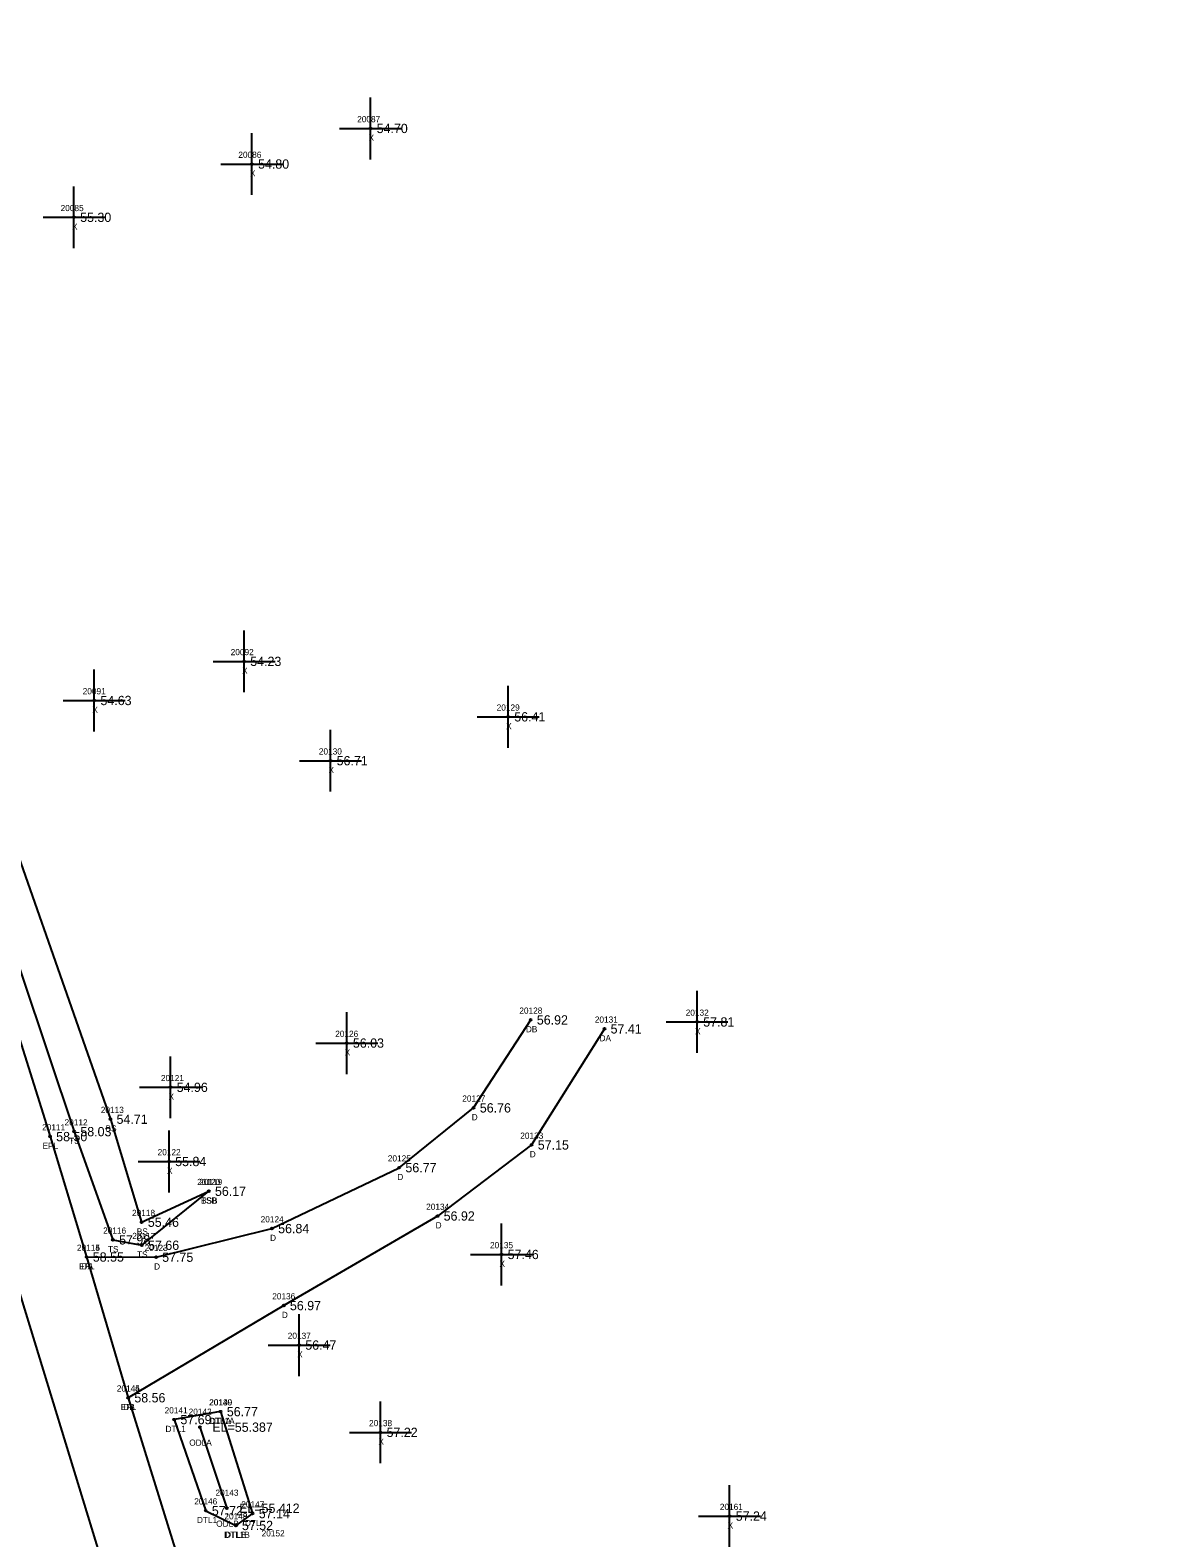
# Model space of a CAD drawing. Extents: x 2396547 to 2397655, y 770185 to 772649.
# Drawn here: x 2396880.4 to 2397062.1, y 771981.7 to 772225.3 of the extents above; entities that cross this region are included whole.
import ezdxf

# ---------------------------------------------------------------- set-up
doc = ezdxf.new("R2010")
doc.units = 0
for name, color, linetype in [('RD_DTM_BkLn1', 7, 'Continuous'), ('RD_DTM_BkLn2', 7, 'Continuous'), ('RD_DTM_BkLn_txCode', 7, 'Continuous'), ('RD_EX_Driveway', 7, 'Continuous'), ('RD_EX_Driveway_txCode', 7, 'Continuous'), ('RD_EX_H2O', 7, 'Continuous'), ('RD_EX_H2O_txCode', 7, 'Continuous'), ('RD_EX_Misc', 7, 'Continuous'), ('RD_EX_Misc_txCode', 7, 'Continuous'), ('RD_EX_Road', 7, 'Continuous'), ('RD_EX_Road_txCode', 7, 'Continuous'), ('RD_EX_TX_Driveway_ELEV', 7, 'Continuous'), ('RD_EX_TX_H2O_ELEV', 7, 'Continuous'), ('RD_EX_TX_Misc_ELEV', 7, 'Continuous'), ('RD_EX_TX_Road_ELEV', 7, 'Continuous'), ('RD_SMD_Locator', 7, 'Continuous')]:
    doc.layers.add(name, color=color, linetype=linetype)

msp = doc.modelspace()

# ---------------------------------------------------------------- linework, layer by layer
at = {"layer": 'RD_DTM_BkLn1'}
msp.add_lwpolyline([(2396669.86, 772614.94), (2396704.28, 772521.49), (2396739.29, 772426.89), (2396775.36, 772328.69), (2396800.21, 772259.35), (2396825.58, 772185.8), (2396852.46, 772104.52), (2396872.48, 772041.55), (2396897.57, 771959.72), (2396918.76, 771888.68), (2396939.09, 771818.34), (2396959.29, 771747.62), (2396993.72, 771617.68), (2397022.56, 771506.67), (2397049.1, 771404.69)], dxfattribs=at)
at = {"layer": 'RD_DTM_BkLn2'}
for points in [[(2396760.04, 772432.43), (2396789.87, 772348.56), (2396819.19, 772264.69), (2396848.46, 772183.36), (2396871.43, 772111.95), (2396893.38, 772049.37), (2396898.43, 772032.73), (2396909.27, 772037.73)], [(2396760.04, 772432.43), (2396760.2, 772413.09), (2396784.34, 772347.64), (2396814.22, 772264.11), (2396842.68, 772182.48), (2396866.31, 772110.61), (2396887.53, 772047.36), (2396893.79, 772029.88), (2396898.47, 772029.01), (2396909.27, 772037.73)]]:
    msp.add_lwpolyline(points, dxfattribs=at)
at = {"layer": 'RD_EX_Driveway'}
for points in [[(2396889.54, 772027.11), (2396900.75, 772027.08), (2396919.48, 772031.7), (2396940.03, 772041.54), (2396952.05, 772051.2), (2396961.26, 772065.41)], [(2396973.17, 772063.96), (2396961.41, 772045.21), (2396946.21, 772033.73), (2396921.38, 772019.26), (2396896.25, 772004.37)]]:
    msp.add_lwpolyline(points, dxfattribs=at)
at = {"layer": 'RD_EX_H2O'}
msp.add_line((2396907.85, 771999.62), (2396912.18, 771986.53), dxfattribs=at)
for points in [[(2396911.19, 772002.13), (2396903.69, 772000.84), (2396908.77, 771986.13), (2396913.63, 771983.74)], [(2396911.19, 772002.13), (2396916.35, 771985.65), (2396913.63, 771983.74)]]:
    msp.add_lwpolyline(points, dxfattribs=at)
at = {"layer": 'RD_EX_Misc'}
for p, q in [((2396935.39, 772204.42), (2396935.39, 772214.42)), ((2396916.23, 772198.67), (2396916.23, 772208.67)), ((2396930.39, 772209.42), (2396940.39, 772209.42)), ((2396911.23, 772203.67), (2396921.23, 772203.67)), ((2396887.5, 772190.06), (2396887.5, 772200.06)), ((2396882.5, 772195.06), (2396892.5, 772195.06)), ((2396914.97, 772118.33), (2396914.97, 772128.33)), ((2396909.97, 772123.33), (2396919.97, 772123.33)), ((2396890.78, 772112.01), (2396890.78, 772122.01)), ((2396957.61, 772109.37), (2396957.61, 772119.37)), ((2396885.78, 772117.01), (2396895.78, 772117.01)), ((2396952.61, 772114.37), (2396962.61, 772114.37)), ((2396928.92, 772102.28), (2396928.92, 772112.28)), ((2396923.92, 772107.28), (2396933.92, 772107.28)), ((2396988.13, 772060.08), (2396988.13, 772070.08)), ((2396931.55, 772056.67), (2396931.55, 772066.67)), ((2396983.13, 772065.08), (2396993.13, 772065.08)), ((2396926.55, 772061.67), (2396936.55, 772061.67)), ((2396903.09, 772049.52), (2396903.09, 772059.52)), ((2396898.09, 772054.52), (2396908.09, 772054.52)), ((2396902.85, 772037.54), (2396902.85, 772047.54)), ((2396897.85, 772042.54), (2396907.85, 772042.54)), ((2396956.54, 772022.52), (2396956.54, 772032.52)), ((2396951.54, 772027.52), (2396961.54, 772027.52)), ((2396923.86, 772007.88), (2396923.86, 772017.88)), ((2396918.86, 772012.88), (2396928.86, 772012.88)), ((2396936.99, 771993.78), (2396936.99, 772003.78)), ((2396931.99, 771998.78), (2396941.99, 771998.78)), ((2396993.38, 771980.25), (2396993.38, 771990.25)), ((2396988.38, 771985.25), (2396998.38, 771985.25))]:
    msp.add_line(p, q, dxfattribs=at)
at = {"layer": 'RD_EX_Road'}
msp.add_lwpolyline([(2396680.92, 772617.84), (2396715.6, 772525.73), (2396750.68, 772430.62), (2396786.3, 772332.21), (2396811.38, 772263.31), (2396839.69, 772181.74), (2396863.75, 772109.83), (2396883.63, 772046.56), (2396889.54, 772027.11), (2396896.25, 772004.37), (2396904.34, 771978.33), (2396908.24, 771964.89), (2396921.74, 771919.68), (2396927.03, 771902.11), (2396950.2, 771821.74), (2396970.47, 771750.68), (2396978.33, 771721.29), (2396990.58, 771675.04), (2397004.94, 771620.49), (2397034.26, 771508.8), (2397061.11, 771410.49), (2397060.64, 771407.04), (2397062.07, 771407.67)], dxfattribs=at)
at = {"layer": 'RD_SMD_Locator'}
for centre in [(2396935.39, 772209.42), (2396916.23, 772203.67), (2396887.5, 772195.06), (2396914.97, 772123.33), (2396890.78, 772117.01), (2396957.61, 772114.37), (2396928.92, 772107.28), (2396961.26, 772065.41), (2396973.17, 772063.96), (2396988.13, 772065.08), (2396931.55, 772061.67), (2396903.09, 772054.52), (2396893.38, 772049.37), (2396952.05, 772051.2), (2396887.53, 772047.36), (2396883.63, 772046.56), (2396961.41, 772045.21), (2396902.85, 772042.54), (2396940.03, 772041.54), (2396909.27, 772037.73), (2396909.27, 772037.73), (2396898.43, 772032.73), (2396946.21, 772033.73), (2396893.79, 772029.88), (2396919.48, 772031.7), (2396898.47, 772029.01), (2396956.54, 772027.52), (2396889.54, 772027.11), (2396889.54, 772027.11), (2396900.75, 772027.08), (2396921.38, 772019.26), (2396923.86, 772012.88), (2396896.25, 772004.37), (2396896.25, 772004.37), (2396903.69, 772000.84), (2396911.19, 772002.13), (2396911.19, 772002.13), (2396907.85, 771999.62), (2396936.99, 771998.78), (2396908.77, 771986.13), (2396912.18, 771986.53), (2396913.63, 771983.74), (2396913.63, 771983.74), (2396916.35, 771985.65), (2396993.38, 771985.25)]:
    msp.add_circle(centre, 0.15, dxfattribs=at)

# ---------------------------------------------------------------- texts
at = {"layer": 'RD_DTM_BkLn_txCode'}
for s, p in [('20112', (2396885.98, 772048.36)), ('20113', (2396891.83, 772050.37)), ('BS', (2396892.6, 772047.37)), ('TS', (2396886.73, 772045.36)), ('20120', (2396907.4, 772038.73)), ('20119', (2396907.72, 772038.73)), ('20118', (2396896.88, 772033.73)), ('TSB', (2396908, 772035.73)), ('BSB', (2396908.02, 772035.73)), ('20116', (2396892.21, 772030.88)), ('20117', (2396896.92, 772030.01)), ('BS', (2396897.65, 772030.73)), ('TS', (2396892.99, 772027.88)), ('TS', (2396897.68, 772027.01))]:
    msp.add_text(s, height=1, dxfattribs=at).set_placement(p)
at = {"layer": 'RD_EX_Driveway_txCode'}
for s, p in [('20128', (2396959.43, 772066.41)), ('DB', (2396960.48, 772063.41)), ('20131', (2396971.62, 772064.96)), ('DA', (2396972.38, 772061.96)), ('20127', (2396950.21, 772052.2)), ('D', (2396951.74, 772049.2)), ('20133', (2396959.58, 772046.21)), ('20125', (2396938.19, 772042.54)), ('D', (2396961.11, 772043.21)), ('D', (2396939.72, 772039.54)), ('20134', (2396944.38, 772034.73)), ('20124', (2396917.65, 772032.7)), ('D', (2396945.91, 772031.73)), ('D', (2396919.17, 772029.7)), ('20115', (2396887.98, 772028.11)), ('20123', (2396898.92, 772028.08)), ('DA', (2396888.74, 772025.11)), ('D', (2396900.44, 772025.08)), ('20136', (2396919.52, 772020.26)), ('D', (2396921.07, 772017.26)), ('20144', (2396894.42, 772005.37)), ('DB', (2396895.47, 772002.37)), ('20152', (2396917.81, 771981.97))]:
    msp.add_text(s, height=1, dxfattribs=at).set_placement(p)
at = {"layer": 'RD_EX_H2O_txCode'}
for s, p in [('20140', (2396909.31, 772003.13)), ('20139', (2396909.35, 772003.13)), ('20141', (2396902.14, 772001.84)), ('20142', (2396906.02, 772001.62)), ('DTL1A', (2396909.29, 772000.13)), ('DTLA', (2396909.45, 772000.13)), ('DTL1', (2396902.28, 771998.84)), ('ODLA', (2396906.12, 771996.62)), ('20143', (2396910.35, 771988.53)), ('20146', (2396906.92, 771987.13)), ('20147', (2396914.52, 771986.65)), ('DTL1', (2396907.36, 771984.13)), ('ODLB', (2396910.47, 771983.53)), ('20148', (2396911.8, 771984.74)), ('20149', (2396911.8, 771984.74)), ('DTL', (2396915.11, 771983.65)), ('DTL1B', (2396911.75, 771981.74)), ('DTLB', (2396911.91, 771981.74))]:
    msp.add_text(s, height=1, dxfattribs=at).set_placement(p)
at = {"layer": 'RD_EX_Misc_txCode'}
for s, p in [('20087', (2396933.24, 772210.42)), ('X', (2396935.08, 772207.42)), ('20086', (2396914.05, 772204.67)), ('X', (2396915.92, 772201.67)), ('20085', (2396885.34, 772196.06)), ('X', (2396887.18, 772193.06)), ('20092', (2396912.81, 772124.33)), ('X', (2396914.65, 772121.33)), ('20091', (2396888.91, 772118.01)), ('X', (2396890.47, 772115.01)), ('20129', (2396955.77, 772115.37)), ('X', (2396957.29, 772112.37)), ('20130', (2396927.05, 772108.28)), ('X', (2396928.61, 772105.28)), ('20132', (2396986.3, 772066.08)), ('X', (2396987.81, 772063.08)), ('20126', (2396929.69, 772062.67)), ('X', (2396931.23, 772059.67)), ('20121', (2396901.54, 772055.52)), ('X', (2396902.78, 772052.52)), ('20122', (2396901.01, 772043.54)), ('X', (2396902.53, 772040.54)), ('20135', (2396954.7, 772028.52)), ('X', (2396956.22, 772025.52)), ('20137', (2396922.03, 772013.88)), ('X', (2396923.55, 772010.88)), ('20138', (2396935.16, 771999.78)), ('X', (2396936.68, 771996.78)), ('20161', (2396991.81, 771986.25)), ('X', (2396993.07, 771983.25))]:
    msp.add_text(s, height=1, dxfattribs=at).set_placement(p)
at = {"layer": 'RD_EX_Road_txCode'}
for s, p in [('20111', (2396882.36, 772047.56)), ('EPL', (2396882.42, 772044.56)), ('20114', (2396887.98, 772028.11)), ('EPL', (2396888.33, 772025.11)), ('20145', (2396894.42, 772005.37)), ('EPL', (2396895.05, 772002.37))]:
    msp.add_text(s, height=1, dxfattribs=at).set_placement(p)
at = {"layer": 'RD_EX_TX_Driveway_ELEV'}
for s, p in [('56.92', (2396962.26, 772064.66)), ('57.41', (2396974.17, 772063.21)), ('56.76', (2396953.05, 772050.45)), ('57.15', (2396962.41, 772044.46)), ('56.77', (2396941.03, 772040.79)), ('56.84', (2396920.48, 772030.95)), ('56.92', (2396947.21, 772032.98)), ('58.55', (2396890.54, 772026.36)), ('57.75', (2396901.75, 772026.33)), ('56.97', (2396922.38, 772018.51)), ('58.56', (2396897.25, 772003.62))]:
    msp.add_text(s, height=1.5, dxfattribs=at).set_placement(p)
at = {"layer": 'RD_EX_TX_H2O_ELEV'}
for s, p in [('57.69', (2396904.69, 772000.09)), ('56.77', (2396912.19, 772001.38)), ('56.77', (2396912.19, 772001.38)), ('EL=55.387', (2396909.85, 771998.87)), ('57.72', (2396909.77, 771985.38)), ('EL=55.412', (2396914.18, 771985.78)), ('57.14', (2396917.35, 771984.9)), ('57.52', (2396914.63, 771982.99)), ('57.52', (2396914.63, 771982.99))]:
    msp.add_text(s, height=1.5, dxfattribs=at).set_placement(p)
at = {"layer": 'RD_EX_TX_Misc_ELEV'}
for s, p in [('54.70', (2396936.39, 772208.67)), ('54.80', (2396917.23, 772202.92)), ('55.30', (2396888.5, 772194.31)), ('54.23', (2396915.97, 772122.58)), ('54.63', (2396891.78, 772116.26)), ('56.41', (2396958.61, 772113.62)), ('56.71', (2396929.92, 772106.53)), ('57.81', (2396989.13, 772064.33)), ('56.03', (2396932.55, 772060.92)), ('54.96', (2396904.09, 772053.77)), ('54.71', (2396894.38, 772048.62)), ('58.03', (2396888.53, 772046.61)), ('55.84', (2396903.85, 772041.79)), ('56.17', (2396910.27, 772036.98)), ('56.17', (2396910.27, 772036.98)), ('55.46', (2396899.43, 772031.98)), ('57.98', (2396894.79, 772029.13)), ('57.66', (2396899.47, 772028.26)), ('57.46', (2396957.54, 772026.77)), ('56.47', (2396924.86, 772012.13)), ('57.22', (2396937.99, 771998.03)), ('57.24', (2396994.38, 771984.5))]:
    msp.add_text(s, height=1.5, dxfattribs=at).set_placement(p)
at = {"layer": 'RD_EX_TX_Road_ELEV'}
for s, p in [('58.50', (2396884.63, 772045.81)), ('58.55', (2396890.54, 772026.36)), ('58.56', (2396897.25, 772003.62))]:
    msp.add_text(s, height=1.5, dxfattribs=at).set_placement(p)

doc.saveas('drawing.dxf')
